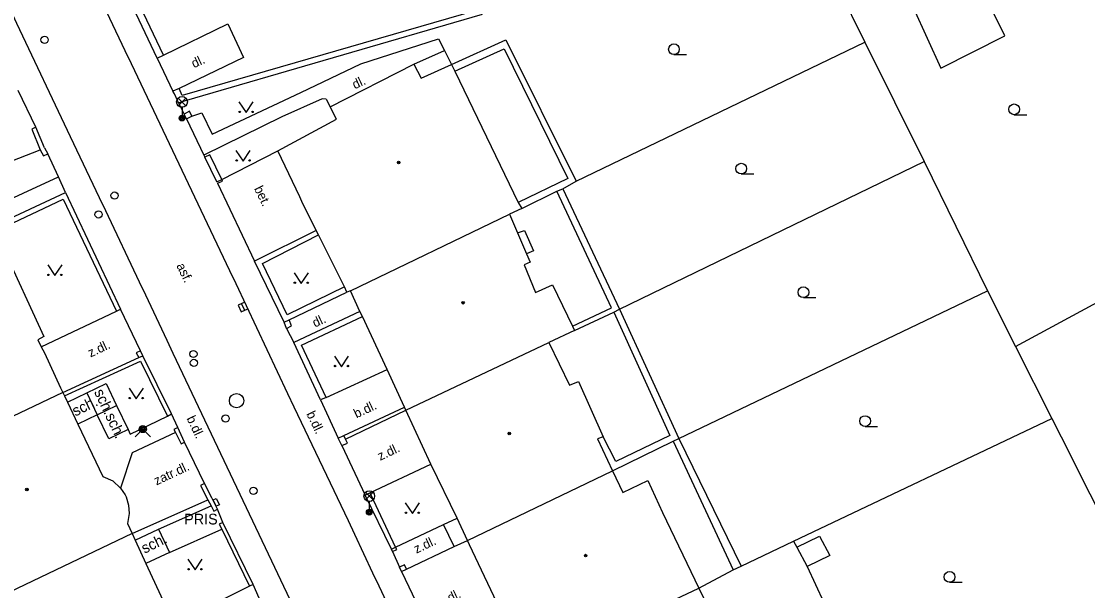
# Model space of a CAD drawing. Extents: x -600391 to -599491, y -1160176 to -1159402.
# Drawn here: x -600225 to -600150.5, y -1159734.3 to -1159694.5 of the extents above; entities that cross this region are included whole.
import ezdxf

# ---------------------------------------------------------------- set-up
doc = ezdxf.new("R2010")
doc.units = 0
for name, color, linetype in [('Level 10', 7, 'Continuous'), ('Level 11', 7, 'Continuous'), ('Level 24', 7, 'Continuous'), ('Level 27', 7, 'Continuous'), ('Level 28', 7, 'Continuous'), ('Level 31', 7, 'Continuous'), ('Level 33', 7, 'Continuous'), ('Level 36', 7, 'Continuous'), ('Level 39', 7, 'Continuous'), ('Level 40', 7, 'Continuous'), ('Level 41', 7, 'Continuous'), ('Level 42', 7, 'Continuous'), ('Level 5', 7, 'Continuous'), ('Level 7', 7, 'Continuous'), ('Level 8', 7, 'Continuous')]:
    doc.layers.add(name, color=color, linetype=linetype)

msp = doc.modelspace()

# ---------------------------------------------------------------- linework, layer by layer
at = {"layer": 'Level 10'}
for points in [[(-600197.66, -1159738.93), (-600199.99, -1159733.97), (-600200.43, -1159733.05), (-600201.7, -1159730.35), (-600202.12, -1159729.41), (-600205.92, -1159721.47), (-600206.37, -1159720.55), (-600209.98, -1159712.86), (-600210.42, -1159711.95), (-600217.28, -1159697.51), (-600217.72, -1159696.59), (-600220.08, -1159691.63), (-600220.49, -1159690.73), (-600221.79, -1159688.03), (-600222.22, -1159687.1), (-600223.28, -1159684.84), (-600223.72, -1159683.94)], [(-600229.18, -1159686.5), (-600228.77, -1159687.46), (-600225.74, -1159693.75), (-600225.32, -1159694.67), (-600221.57, -1159702.58), (-600219.55, -1159706.83), (-600219.1, -1159707.74), (-600216.76, -1159712.72), (-600216.32, -1159713.62), (-600214.82, -1159716.8), (-600214.39, -1159717.71), (-600207.52, -1159732.19), (-600207.08, -1159733.09), (-600204.09, -1159739.42)]]:
    msp.add_lwpolyline(points, dxfattribs=at)
at = {"layer": 'Level 11'}
for points in [[(-600162.66, -1159693.62), (-600160.75, -1159697.8), (-600156.28, -1159695.54), (-600158.28, -1159691.52), (-600162.66, -1159693.62)], [(-600215.06, -1159696.9), (-600210.56, -1159694.72), (-600209.46, -1159697.06), (-600213.97, -1159699.23)], [(-600213.07, -1159701.17), (-600212.38, -1159700.92), (-600211.65, -1159702.41), (-600205.46, -1159699.5), (-600201.27, -1159697.51), (-600195.84, -1159695.76)], [(-600195.84, -1159695.76), (-600195.43, -1159696.58), (-600194.93, -1159697.55)], [(-600194.93, -1159697.55), (-600191.14, -1159695.84), (-600186.23, -1159705.69)], [(-600197.58, -1159697.52), (-600195.43, -1159696.58)], [(-600194.7, -1159698.02), (-600191.27, -1159696.47), (-600186.81, -1159705.5), (-600190.29, -1159707.18)], [(-600203.68, -1159699.97), (-600203.97, -1159699.95), (-600206.79, -1159701.21), (-600212.23, -1159703.87)], [(-600203.68, -1159699.97), (-600203.41, -1159700.5)], [(-600210.99, -1159705.57), (-600207.07, -1159703.58)], [(-600236.03, -1159711.68), (-600231.97, -1159709.81), (-600222.39, -1159705.4)], [(-600211.33, -1159705.75), (-600210.99, -1159705.57)], [(-600187.16, -1159706.22), (-600183.2, -1159714.62)], [(-600186.49, -1159715.82), (-600183.77, -1159714.53), (-600187.59, -1159706.4)], [(-600190.32, -1159709.31), (-600189.69, -1159710.76)], [(-600155.55, -1159717.24), (-600142.11, -1159709.97)], [(-600223.59, -1159717.26), (-600218.33, -1159714.76)], [(-600218.33, -1159714.76), (-600218.05, -1159714.63)], [(-600183.6, -1159714.83), (-600179.68, -1159723.45), (-600183.47, -1159725.26), (-600184.34, -1159723.54)], [(-600183.2, -1159714.62), (-600179.05, -1159723.65)], [(-600203.7, -1159720.8), (-600199.44, -1159718.85)], [(-600220.41, -1159720.48), (-600219.06, -1159719.83), (-600218.33, -1159721.35)], [(-600221.76, -1159721.13), (-600220.41, -1159720.48)], [(-600220.41, -1159720.48), (-600219.68, -1159722.01)], [(-600218.33, -1159721.35), (-600217.53, -1159723.04), (-600218.88, -1159723.69), (-600219.68, -1159722.01)], [(-600219.68, -1159722.01), (-600218.33, -1159721.35)], [(-600219.68, -1159722.01), (-600221.04, -1159722.66)], [(-600217.53, -1159723.04), (-600217.38, -1159723.36), (-600214.78, -1159722.11)], [(-600153.01, -1159722.26), (-600152.36, -1159723.54)], [(-600214.22, -1159723.25), (-600217.23, -1159724.65), (-600218.05, -1159727.12)], [(-600179.45, -1159723.85), (-600175.26, -1159732.83)], [(-600179.05, -1159723.65), (-600174.71, -1159732.57)], [(-600200.63, -1159727.45), (-600196.37, -1159725.44)], [(-600215.4, -1159729.99), (-600211.73, -1159728.35)], [(-600195.49, -1159729.67), (-600194.55, -1159729.23)], [(-600217.03, -1159730.76), (-600215.4, -1159729.99), (-600214.63, -1159731.61), (-600216.28, -1159732.39)], [(-600214.63, -1159731.61), (-600210.99, -1159729.98)], [(-600198.84, -1159731.25), (-600195.49, -1159729.67)], [(-600194.75, -1159731.2), (-600195.49, -1159729.67)], [(-600171.05, -1159730.83), (-600170.82, -1159731.24)], [(-600170.82, -1159731.24), (-600169.24, -1159730.48), (-600168.52, -1159731.82), (-600170.09, -1159732.6)], [(-600199.13, -1159731.39), (-600198.84, -1159731.25)], [(-600170.82, -1159731.24), (-600170.09, -1159732.6)], [(-600170.09, -1159732.6), (-600166.61, -1159740.12), (-600171.26, -1159742.42)], [(-600208.8, -1159733.85), (-600209.05, -1159733.97)]]:
    msp.add_lwpolyline(points, dxfattribs=at)
at = {"layer": 'Level 24'}
msp.add_lwpolyline([(-600211.59, -1159727.95), (-600211.37, -1159727.84), (-600211.15, -1159728.28), (-600211.38, -1159728.39), (-600211.59, -1159727.95)], dxfattribs=at)
at = {"layer": 'Level 27'}
msp.add_line((-600209.604, -1159714.253), (-600209.396, -1159714.707), dxfattribs=at)
msp.add_lwpolyline([(-600209.831, -1159714.357), (-600209.623, -1159714.811), (-600209.169, -1159714.603), (-600209.377, -1159714.149)], close=True, dxfattribs=at)
msp.add_circle((-600209.95, -1159721.02), 0.5, dxfattribs=at)
at = {"layer": 'Level 28'}
for centre in [(-600223.36, -1159695.83), (-600218.47, -1159706.7), (-600212.96, -1159717.76), (-600212.93, -1159718.38), (-600210.72, -1159722.26), (-600208.77, -1159727.31)]:
    msp.add_circle(centre, 0.25, dxfattribs=at)
at = {"layer": 'Level 31'}
msp.add_lwpolyline([(-600217.03, -1159723.53), (-600216.5, -1159723), (-600215.97, -1159723.53)], dxfattribs=at)
for centre, radius in [((-600219.59, -1159708.02), 0.25), ((-600216.5, -1159723), 0.25), ((-600216.5, -1159723), 0.18), ((-600216.5, -1159723), 0.11)]:
    msp.add_circle(centre, radius, dxfattribs=at)
at = {"layer": 'Level 33'}
for p, q in [((-600214.025, -1159700.43), (-600213.495, -1159699.9)), ((-600214.025, -1159699.9), (-600213.495, -1159700.43)), ((-600213.76, -1159700.54), (-600213.76, -1159701.29)), ((-600200.945, -1159727.94), (-600200.415, -1159727.41)), ((-600200.945, -1159727.41), (-600200.415, -1159727.94)), ((-600200.68, -1159728.05), (-600200.68, -1159728.8))]:
    msp.add_line(p, q, dxfattribs=at)
for centre, radius in [((-600213.76, -1159700.165), 0.375), ((-600213.76, -1159701.29), 0.2), ((-600213.76, -1159701.29), 0.145), ((-600213.76, -1159701.29), 0.0876), ((-600200.68, -1159727.675), 0.375), ((-600200.68, -1159728.8), 0.2), ((-600200.68, -1159728.8), 0.145), ((-600200.68, -1159728.8), 0.0876)]:
    msp.add_circle(centre, radius, dxfattribs=at)
at = {"layer": 'Level 36'}
for p, q in [((-600179.4, -1159696.865), (-600178.525, -1159696.865)), ((-600155.64, -1159701.055), (-600154.765, -1159701.055)), ((-600174.7, -1159705.195), (-600173.825, -1159705.195)), ((-600170.36, -1159713.825), (-600169.485, -1159713.825)), ((-600166.05, -1159722.815), (-600165.175, -1159722.815)), ((-600160.15, -1159733.695), (-600159.275, -1159733.695))]:
    msp.add_line(p, q, dxfattribs=at)
for points in [[(-600209.78, -1159700.16), (-600209.28, -1159700.91), (-600208.78, -1159700.16)], [(-600209.99, -1159703.55), (-600209.49, -1159704.3), (-600208.99, -1159703.55)], [(-600223.14, -1159711.54), (-600222.64, -1159712.29), (-600222.14, -1159711.54)], [(-600205.93, -1159712.09), (-600205.43, -1159712.84), (-600204.93, -1159712.09)], [(-600203.12, -1159717.9), (-600202.62, -1159718.65), (-600202.12, -1159717.9)], [(-600217.46, -1159720.14), (-600216.96, -1159720.89), (-600216.46, -1159720.14)], [(-600198.17, -1159728.14), (-600197.67, -1159728.89), (-600197.17, -1159728.14)], [(-600213.35, -1159732.08), (-600212.85, -1159732.83), (-600212.35, -1159732.08)]]:
    msp.add_lwpolyline(points, dxfattribs=at)
for centre, radius in [((-600179.4, -1159696.49), 0.375), ((-600155.64, -1159700.68), 0.375), ((-600209.73, -1159700.86), 0.05), ((-600208.831, -1159700.86), 0.05), ((-600209.94, -1159704.25), 0.05), ((-600209.041, -1159704.25), 0.05), ((-600174.7, -1159704.82), 0.375), ((-600223.09, -1159712.24), 0.05), ((-600222.191, -1159712.24), 0.05), ((-600205.88, -1159712.79), 0.05), ((-600204.981, -1159712.79), 0.05), ((-600170.36, -1159713.45), 0.375), ((-600203.07, -1159718.6), 0.05), ((-600202.171, -1159718.6), 0.05), ((-600217.41, -1159720.84), 0.05), ((-600216.511, -1159720.84), 0.05), ((-600166.05, -1159722.44), 0.375), ((-600198.12, -1159728.84), 0.05), ((-600197.221, -1159728.84), 0.05), ((-600213.3, -1159732.78), 0.05), ((-600212.401, -1159732.78), 0.05), ((-600160.15, -1159733.32), 0.375)]:
    msp.add_circle(centre, radius, dxfattribs=at)
at = {"layer": 'Level 39'}
for centre, radius in [((-600198.63, -1159704.39), 0.09), ((-600198.63, -1159704.39), 0.0398), ((-600194.13, -1159714.18), 0.09), ((-600194.13, -1159714.18), 0.0398), ((-600190.9, -1159723.31), 0.09), ((-600190.9, -1159723.31), 0.0398), ((-600224.59, -1159727.22), 0.09), ((-600224.59, -1159727.22), 0.0398), ((-600185.57, -1159731.83), 0.09), ((-600185.57, -1159731.83), 0.0398)]:
    msp.add_circle(centre, radius, dxfattribs=at)
at = {"layer": 'Level 5'}
for points in [[(-600203.41, -1159700.5), (-600197.58, -1159697.52)], [(-600197.58, -1159697.52), (-600197.06, -1159698.51)], [(-600197.06, -1159698.51), (-600194.93, -1159697.55)], [(-600194.93, -1159697.55), (-600194.7, -1159698.02)], [(-600194.7, -1159698.02), (-600190.29, -1159707.18)], [(-600202.98, -1159701.37), (-600203.41, -1159700.5)], [(-600207.07, -1159703.58), (-600202.98, -1159701.37)], [(-600205.52, -1159706.79), (-600207.07, -1159703.58)], [(-600205.38, -1159707.11), (-600205.52, -1159706.79)], [(-600204.39, -1159709.13), (-600205.38, -1159707.11)], [(-600190.03, -1159707.61), (-600190.88, -1159708.01)], [(-600190.29, -1159707.18), (-600190.03, -1159707.61)], [(-600202, -1159713.34), (-600190.88, -1159708.01)], [(-600190.88, -1159708.01), (-600190.32, -1159709.31)], [(-600204.22, -1159709.45), (-600204.39, -1159709.13)], [(-600190.32, -1159709.31), (-600189.83, -1159709.14)], [(-600189.83, -1159709.14), (-600189.21, -1159710.57)], [(-600202.42, -1159713.07), (-600204.22, -1159709.45)], [(-600226.31, -1159710.22), (-600223.41, -1159716.54)], [(-600189.21, -1159710.57), (-600189.69, -1159710.76)], [(-600189.45, -1159711.34), (-600189.87, -1159711.54)], [(-600189.69, -1159710.76), (-600189.45, -1159711.34)], [(-600189.87, -1159711.54), (-600189.07, -1159713.47)], [(-600189.07, -1159713.47), (-600187.89, -1159712.94)], [(-600187.89, -1159712.94), (-600186.49, -1159715.82)], [(-600202.24, -1159713.44), (-600202.42, -1159713.07)], [(-600202, -1159713.34), (-600202.24, -1159713.44)], [(-600201.33, -1159714.79), (-600202, -1159713.34)], [(-600201.16, -1159715.15), (-600201.33, -1159714.79)], [(-600198.23, -1159721.47), (-600199.44, -1159718.85), (-600201.16, -1159715.15)], [(-600186.49, -1159715.82), (-600186.35, -1159716.11)], [(-600223.41, -1159716.54), (-600223.83, -1159716.76)], [(-600186.35, -1159716.11), (-600188.15, -1159716.96)], [(-600223.83, -1159716.76), (-600223.59, -1159717.26)], [(-600223.59, -1159717.26), (-600223.37, -1159717.68)], [(-600198.13, -1159721.68), (-600188.15, -1159716.96)], [(-600188.15, -1159716.96), (-600186.7, -1159719.93)], [(-600223.37, -1159717.68), (-600222.25, -1159720.11)], [(-600186.7, -1159719.93), (-600186.07, -1159719.68)], [(-600186.07, -1159719.68), (-600184.34, -1159723.54)], [(-600222.25, -1159720.11), (-600222.09, -1159720.45)], [(-600222.09, -1159720.45), (-600232.65, -1159725.48)], [(-600222.09, -1159720.45), (-600221.97, -1159720.69)], [(-600221.97, -1159720.69), (-600221.76, -1159721.13)], [(-600221.76, -1159721.13), (-600221.04, -1159722.66)], [(-600198.13, -1159721.68), (-600198.23, -1159721.47)], [(-600196.37, -1159725.44), (-600198.13, -1159721.68)], [(-600221.04, -1159722.66), (-600219.28, -1159726.31)], [(-600184.34, -1159723.54), (-600184.75, -1159723.67)], [(-600184.75, -1159723.67), (-600183.7, -1159725.92)], [(-600194.55, -1159729.23), (-600196.37, -1159725.44)], [(-600219.28, -1159726.31), (-600218.59, -1159726.62)], [(-600193.83, -1159730.77), (-600183.7, -1159725.92)], [(-600183.7, -1159725.92), (-600182.98, -1159727.43)], [(-600218.59, -1159726.62), (-600218.05, -1159727.12)], [(-600218.05, -1159727.12), (-600217.74, -1159727.58)], [(-600182.98, -1159727.43), (-600181.23, -1159726.59)], [(-600181.23, -1159726.59), (-600180.2, -1159728.82)], [(-600217.74, -1159727.58), (-600217.66, -1159727.74)], [(-600217.66, -1159727.74), (-600217.5, -1159728.31)], [(-600217.5, -1159728.31), (-600217.44, -1159728.9)], [(-600217.44, -1159728.9), (-600217.56, -1159729.58)], [(-600193.83, -1159730.77), (-600194.55, -1159729.23)], [(-600180.2, -1159728.82), (-600177.67, -1159734.1)], [(-600217.56, -1159729.58), (-600217.25, -1159730.3)], [(-600217.25, -1159730.3), (-600227.97, -1159735.41)], [(-600217.25, -1159730.3), (-600217.03, -1159730.76)], [(-600217.03, -1159730.76), (-600216.28, -1159732.39)], [(-600193.68, -1159731.08), (-600193.83, -1159730.77)], [(-600190.39, -1159738.01), (-600191.35, -1159736), (-600193.68, -1159731.08)], [(-600216.28, -1159732.39), (-600214.33, -1159736.59)], [(-600189.55, -1159739.72), (-600177.67, -1159734.1)], [(-600177.67, -1159734.1), (-600176.87, -1159735.72)]]:
    msp.add_lwpolyline(points, dxfattribs=at)
at = {"layer": 'Level 7'}
for points in [[(-600197.36, -1159683.08), (-600197.68, -1159683.24), (-600193.22, -1159693.79), (-600213.74, -1159699.72), (-600213.97, -1159699.23), (-600214.39, -1159699.41)], [(-600169.84, -1159688.34), (-600166.06, -1159695.99)], [(-600215.5, -1159697.11), (-600215.06, -1159696.9), (-600217.14, -1159692.47), (-600217.58, -1159692.67)], [(-600215.5, -1159697.11), (-600217.58, -1159692.67)], [(-600214, -1159700.22), (-600213.58, -1159700.1), (-600192.77, -1159694.04)], [(-600186.23, -1159705.69), (-600166.06, -1159695.99)], [(-600166.06, -1159695.99), (-600161.93, -1159704.32)], [(-600214, -1159700.22), (-600214.08, -1159700.06), (-600214.29, -1159699.61), (-600214.39, -1159699.41)], [(-600213.45, -1159701.35), (-600213.07, -1159701.17), (-600213.23, -1159700.82), (-600213.62, -1159701.01)], [(-600213.45, -1159701.35), (-600213.62, -1159701.01)], [(-600223.96, -1159701.93), (-600224.26, -1159702.07), (-600223.67, -1159703.51)], [(-600223.36, -1159703.38), (-600223.96, -1159701.93)], [(-600244.92, -1159711.74), (-600241.04, -1159710.27), (-600223.67, -1159703.51)], [(-600223.67, -1159703.51), (-600223.43, -1159703.93), (-600223.14, -1159703.78)], [(-600223.36, -1159703.38), (-600223.14, -1159703.78)], [(-600210.99, -1159705.57), (-600211.81, -1159703.85), (-600212.16, -1159704.02)], [(-600211.33, -1159705.75), (-600212.16, -1159704.02)], [(-600183.2, -1159714.62), (-600161.93, -1159704.32)], [(-600161.93, -1159704.32), (-600157.51, -1159713.35)], [(-600211.28, -1159705.84), (-600210.93, -1159705.69), (-600210.99, -1159705.57)], [(-600187.59, -1159706.4), (-600187.16, -1159706.22)], [(-600187.16, -1159706.22), (-600186.23, -1159705.69)], [(-600231.44, -1159710.94), (-600221.89, -1159706.48)], [(-600231.28, -1159711.3), (-600222.07, -1159706.96), (-600218.33, -1159714.76)], [(-600221.89, -1159706.48), (-600218.05, -1159714.63)], [(-600190.03, -1159707.61), (-600187.59, -1159706.4)], [(-600204.39, -1159709.13), (-600208.69, -1159711.28)], [(-600202.42, -1159713.07), (-600206.41, -1159715.03), (-600208.14, -1159711.44), (-600204.22, -1159709.45)], [(-600206.62, -1159715.54), (-600208.69, -1159711.28)], [(-600206.28, -1159715.38), (-600202.24, -1159713.44)], [(-600179.05, -1159723.65), (-600157.51, -1159713.35)], [(-600157.51, -1159713.35), (-600155.55, -1159717.24), (-600153.01, -1159722.26)], [(-600201.33, -1159714.79), (-600205.96, -1159716.95)], [(-600203.7, -1159720.8), (-600205.42, -1159717.14), (-600201.16, -1159715.15)], [(-600186.35, -1159716.11), (-600183.6, -1159714.83)], [(-600183.6, -1159714.83), (-600183.2, -1159714.62)], [(-600206.62, -1159715.54), (-600206.28, -1159715.38)], [(-600206.47, -1159715.97), (-600206.62, -1159715.54)], [(-600206.47, -1159715.97), (-600206.12, -1159715.8), (-600206.28, -1159715.38)], [(-600203.7, -1159720.8), (-600204.09, -1159720.97), (-600205.96, -1159716.95)], [(-600222.09, -1159720.45), (-600216.78, -1159718.01)], [(-600216.66, -1159717.53), (-600216.96, -1159717.67), (-600216.78, -1159718.01)], [(-600216.78, -1159718.01), (-600216.49, -1159717.88)], [(-600216.49, -1159717.88), (-600216.66, -1159717.53)], [(-600214.49, -1159721.94), (-600216.49, -1159717.88)], [(-600221.97, -1159720.69), (-600216.66, -1159718.26), (-600214.78, -1159722.11), (-600214.49, -1159721.94)], [(-600202.45, -1159723.44), (-600198.23, -1159721.47)], [(-600202.33, -1159723.71), (-600198.13, -1159721.68)], [(-600171.05, -1159730.83), (-600153.01, -1159722.26)], [(-600214.05, -1159722.89), (-600214.33, -1159723.02), (-600214.22, -1159723.25), (-600213.83, -1159724.04), (-600213.58, -1159723.91)], [(-600213.58, -1159723.91), (-600214.05, -1159722.89)], [(-600202.85, -1159723.63), (-600202.45, -1159723.44)], [(-600202.59, -1159724.15), (-600202.85, -1159723.63)], [(-600202.59, -1159724.15), (-600202.21, -1159723.98), (-600202.33, -1159723.71), (-600202.45, -1159723.44)], [(-600183.7, -1159725.92), (-600179.45, -1159723.85)], [(-600179.45, -1159723.85), (-600179.05, -1159723.65)], [(-600152.36, -1159723.54), (-600150.35, -1159727.52), (-600146.3, -1159735.55)], [(-600212.18, -1159726.79), (-600212.46, -1159726.94), (-600211.95, -1159727.93)], [(-600211.68, -1159727.8), (-600212.18, -1159726.79)], [(-600211.28, -1159728.59), (-600211.68, -1159727.8)], [(-600200.97, -1159727.61), (-600200.63, -1159727.45)], [(-600199.13, -1159731.39), (-600200.97, -1159727.61)], [(-600198.84, -1159731.25), (-600200.56, -1159727.62), (-600200.63, -1159727.45)], [(-600217.25, -1159730.3), (-600211.95, -1159727.93)], [(-600211.95, -1159727.93), (-600211.73, -1159728.35), (-600211.54, -1159728.73), (-600211.28, -1159728.59)], [(-600210.9, -1159729.52), (-600211.16, -1159729.64), (-600210.99, -1159729.98), (-600209.05, -1159733.97)], [(-600208.8, -1159733.85), (-600210.9, -1159729.52)], [(-600194.75, -1159731.2), (-600193.83, -1159730.77)], [(-600174.71, -1159732.57), (-600171.05, -1159730.83)], [(-600199.05, -1159731.55), (-600199.13, -1159731.39)], [(-600199.05, -1159731.55), (-600198.76, -1159731.41)], [(-600198.76, -1159731.41), (-600198.84, -1159731.25)], [(-600198.09, -1159732.77), (-600194.75, -1159731.2)], [(-600198.09, -1159732.77), (-600198.23, -1159732.47), (-600198.57, -1159732.63)], [(-600198.43, -1159732.93), (-600198.57, -1159732.63)], [(-600198.43, -1159732.93), (-600198.09, -1159732.77)], [(-600177.67, -1159734.1), (-600175.26, -1159732.83)], [(-600175.26, -1159732.83), (-600174.71, -1159732.57)], [(-600209.05, -1159733.97), (-600214.33, -1159736.59)]]:
    msp.add_lwpolyline(points, dxfattribs=at)
at = {"layer": 'Level 8'}
for points in [[(-600215.5, -1159697.11), (-600214.39, -1159699.41)], [(-600223.96, -1159701.93), (-600225.2, -1159699.37)], [(-600214, -1159700.22), (-600213.62, -1159701.01)], [(-600213.45, -1159701.35), (-600212.23, -1159703.87), (-600212.16, -1159704.02)], [(-600221.89, -1159706.48), (-600222.39, -1159705.4), (-600223.14, -1159703.78)], [(-600211.28, -1159705.84), (-600208.69, -1159711.28)], [(-600216.66, -1159717.53), (-600218.05, -1159714.63)], [(-600206.47, -1159715.97), (-600205.96, -1159716.95)], [(-600204.09, -1159720.97), (-600202.85, -1159723.63)], [(-600214.05, -1159722.89), (-600214.49, -1159721.94)], [(-600212.18, -1159726.79), (-600213.58, -1159723.91)], [(-600202.59, -1159724.15), (-600200.97, -1159727.61)], [(-600210.9, -1159729.52), (-600211.28, -1159728.59)], [(-600199.05, -1159731.55), (-600198.57, -1159732.63)], [(-600198.43, -1159732.93), (-600195.92, -1159738.19)], [(-600207.63, -1159736.51), (-600208.8, -1159733.85)]]:
    msp.add_lwpolyline(points, dxfattribs=at)

# ---------------------------------------------------------------- texts
at = {"layer": 'Level 40'}
for s, rotation, p in [('dl.', 25.15616, (-600212.92, -1159697.82)), ('dl.', 25.15616, (-600201.69, -1159699.29)), ('bet.', 295.77432, (-600208.74, -1159706.21)), ('asf.', 295.58, (-600214.17, -1159711.59)), ('dl.', 25.15616, (-600204.47, -1159715.92)), ('z.dl.', 25.15616, (-600220.15, -1159718.01)), ('b.dl.', 25.15616, (-600201.58, -1159722.26)), ('b.dl. ', 295.58, (-600205.09, -1159721.93)), ('b.dl. ', 295.38, (-600213.46, -1159722.25)), ('z.dl.', 25.15616, (-600199.92, -1159725.22)), ('zatr.dl.', 25.15616, (-600215.54, -1159726.94)), ('z.dl.', 25.15616, (-600197.39, -1159731.7)), ('dl.', 25.15616, (-600195.04, -1159735.11))]:
    msp.add_text(s, height=0.65, rotation=rotation, dxfattribs=at).set_placement(p)
at = {"layer": 'Level 41'}
msp.add_text('PRIS', height=0.75, dxfattribs=at).set_placement((-600213.61, -1159729.66))
msp.add_text('PRIS', height=0.75, dxfattribs=at).set_placement((-600213.61, -1159729.66))
at = {"layer": 'Level 42'}
for rotation, p in [(295, (-600219.92, -1159720.4)), (26, (-600221.21, -1159722.13)), (295, (-600219.14, -1159722.07)), (26, (-600216.38, -1159731.71))]:
    msp.add_text('sch.', height=0.75, rotation=rotation, dxfattribs=at).set_placement(p)

doc.saveas('drawing.dxf')
